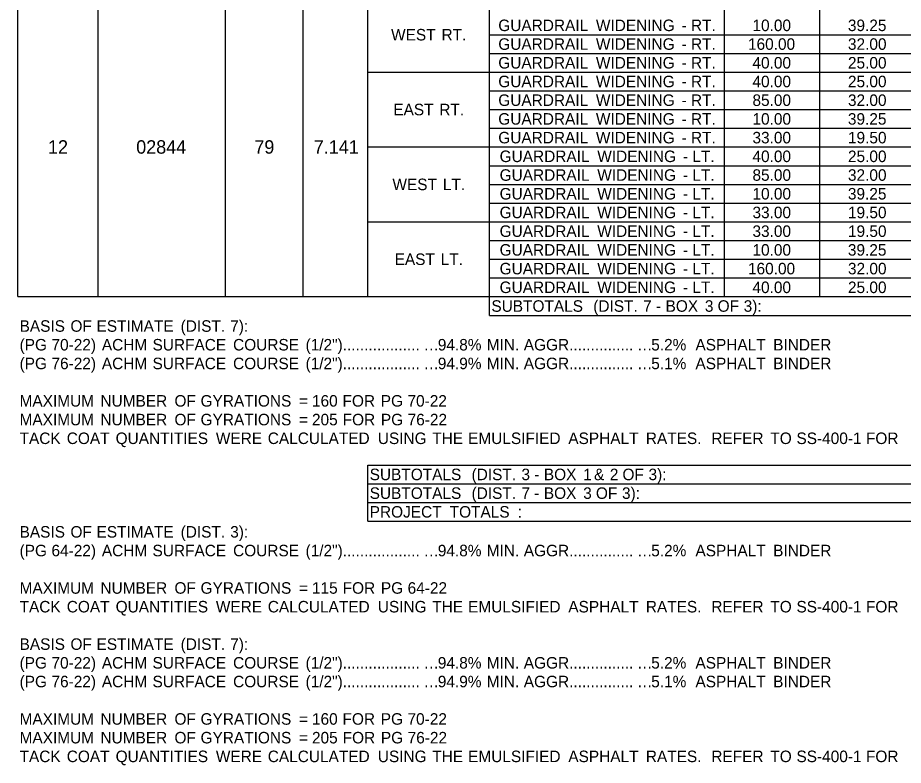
# Model space of a CAD drawing. Extents: x 544478 to 1930787, y -1948294 to 596640.
# Drawn here: x 554061.9 to 554523.1, y -1946916.2 to -1946526.7 of the extents above; entities that cross this region are included whole.
import ezdxf

# ---------------------------------------------------------------- set-up
doc = ezdxf.new("R2010")
doc.units = 0
doc.layers.add('Default', color=7, linetype='Continuous')

msp = doc.modelspace()

# ---------------------------------------------------------------- linework, layer by layer
at = {"layer": 'Default'}
for p, q in [((554061.9, -1946672.02), (554061.9, -1946149.42)), ((554244.23, -1946672.02), (554244.23, -1946149.42)), ((554307.6, -1946681.77), (554307.6, -1946149.42)), ((554429.97, -1946672.02), (554429.97, -1946149.42)), ((554479.69, -1946672.02), (554479.69, -1946149.42)), ((554479.69, -1946672.02), (554479.69, -1946194.27)), ((554103.83, -1946672.02), (554103.83, -1946204.02)), ((554170.13, -1946672.02), (554170.13, -1946204.02)), ((554210.59, -1946672.02), (554210.59, -1946204.02)), ((554429.97, -1946672.02), (554429.97, -1946204.02)), ((554307.6, -1946535.52), (554884.32, -1946535.52)), ((554307.6, -1946545.27), (554884.32, -1946545.27)), ((554244.23, -1946555.02), (554307.6, -1946555.02)), ((554307.6, -1946555.02), (554884.32, -1946555.02)), ((554307.6, -1946564.77), (554884.32, -1946564.77)), ((554307.6, -1946574.52), (554884.32, -1946574.52)), ((554307.6, -1946584.27), (554884.32, -1946584.27)), ((554244.23, -1946594.02), (554307.6, -1946594.02)), ((554307.6, -1946594.02), (554884.32, -1946594.02)), ((554307.6, -1946603.77), (554884.32, -1946603.77)), ((554307.6, -1946613.52), (554884.32, -1946613.52)), ((554307.6, -1946623.27), (554884.32, -1946623.27)), ((554244.23, -1946633.02), (554307.6, -1946633.02)), ((554307.6, -1946633.02), (554581.58, -1946633.02)), ((554307.6, -1946642.77), (554884.32, -1946642.77)), ((554307.6, -1946652.52), (554581.58, -1946652.52)), ((554307.6, -1946662.27), (554581.58, -1946662.27)), ((554061.9, -1946672.02), (554884.32, -1946672.02)), ((554307.6, -1946681.77), (554307.6, -1946672.02)), ((554307.6, -1946681.77), (554884.32, -1946681.77)), ((554244.23, -1946759.77), (554834.59, -1946759.77)), ((554244.23, -1946759.77), (554884.32, -1946759.77)), ((554244.23, -1946789.02), (554244.23, -1946759.77)), ((554244.23, -1946789.02), (554244.23, -1946759.77)), ((554244.23, -1946769.52), (554884.32, -1946769.52)), ((554244.23, -1946779.27), (554884.32, -1946779.27)), ((554244.23, -1946789.02), (554884.32, -1946789.02))]:
    msp.add_line(p, q, dxfattribs=at)

# ---------------------------------------------------------------- texts
for s, height, p in [('GUARDRAIL', 6, (554312.17, -1946533.65)), (' WIDENING', 6, (554360.79, -1946533.65)), (' RT.', 6, (554410.29, -1946533.65)), ('10.00', 6, (554444.54, -1946533.65)), ('39.25', 6, (554494.24, -1946533.65)), ('WEST', 6, (554256.34, -1946538.52)), (' RT.', 6, (554280.39, -1946538.52)), (' -', 6, (554405.44, -1946533.65)), ('GUARDRAIL', 6, (554312.17, -1946543.4)), (' WIDENING', 6, (554360.79, -1946543.4)), (' RT.', 6, (554410.29, -1946543.4)), ('160.00', 6, (554442.21, -1946543.4)), ('32.00', 6, (554494.27, -1946543.4)), (' -', 6, (554405.44, -1946543.4)), ('GUARDRAIL', 6, (554312.17, -1946553.15)), (' WIDENING', 6, (554360.79, -1946553.15)), (' RT.', 6, (554410.29, -1946553.15)), ('40.00', 6, (554444.54, -1946553.15)), ('25.00', 6, (554494.27, -1946553.15)), (' -', 6, (554405.44, -1946553.15)), ('GUARDRAIL', 6, (554312.17, -1946562.9)), (' WIDENING', 6, (554360.79, -1946562.9)), (' RT.', 6, (554410.29, -1946562.9)), ('40.00', 6, (554444.54, -1946562.9)), ('25.00', 6, (554494.27, -1946562.9)), (' -', 6, (554405.44, -1946562.9)), ('GUARDRAIL', 6, (554312.17, -1946572.65)), (' WIDENING', 6, (554360.79, -1946572.65)), (' -', 6, (554405.44, -1946572.65)), (' RT.', 6, (554410.29, -1946572.65)), ('85.00', 6, (554444.54, -1946572.65)), ('32.00', 6, (554494.27, -1946572.65)), ('EAST', 6, (554257.5, -1946577.52)), (' RT.', 6, (554279.23, -1946577.52)), ('GUARDRAIL', 6, (554312.17, -1946582.4)), (' WIDENING', 6, (554360.79, -1946582.4)), (' -', 6, (554405.44, -1946582.4)), (' RT.', 6, (554410.29, -1946582.4)), ('10.00', 6, (554444.54, -1946582.4)), ('39.25', 6, (554494.24, -1946582.4)), ('GUARDRAIL', 6, (554312.17, -1946592.15)), (' WIDENING', 6, (554360.79, -1946592.15)), (' RT.', 6, (554410.29, -1946592.15)), ('33.00', 6, (554444.54, -1946592.15)), ('19.50', 6, (554494.27, -1946592.15)), ('12', 7, (554077.69, -1946597.52)), ('02844', 7, (554123.62, -1946597.52)), ('79', 7, (554185.14, -1946597.52)), ('7.141', 7, (554216.08, -1946597.52)), (' -', 6, (554405.44, -1946592.15)), ('GUARDRAIL', 6, (554312.87, -1946601.9)), (' WIDENING', 6, (554361.49, -1946601.9)), (' LT.', 6, (554410.99, -1946601.9)), ('40.00', 6, (554444.54, -1946601.9)), ('25.00', 6, (554494.27, -1946601.9)), (' -', 6, (554406.14, -1946601.9)), ('GUARDRAIL', 6, (554312.87, -1946611.65)), (' WIDENING', 6, (554361.49, -1946611.65)), (' LT.', 6, (554410.99, -1946611.65)), ('85.00', 6, (554444.54, -1946611.65)), ('32.00', 6, (554494.27, -1946611.65)), ('WEST', 6, (554257.04, -1946616.52)), (' LT.', 6, (554281.09, -1946616.52)), (' -', 6, (554406.14, -1946611.65)), ('GUARDRAIL', 6, (554312.87, -1946621.4)), (' WIDENING', 6, (554361.49, -1946621.4)), (' LT.', 6, (554410.99, -1946621.4)), ('10.00', 6, (554444.54, -1946621.4)), ('39.25', 6, (554494.24, -1946621.4)), (' -', 6, (554406.14, -1946621.4)), ('GUARDRAIL', 6, (554312.87, -1946631.15)), (' WIDENING', 6, (554361.49, -1946631.15)), (' LT.', 6, (554410.99, -1946631.15)), ('33.00', 6, (554444.54, -1946631.15)), ('19.50', 6, (554494.27, -1946631.15)), (' -', 6, (554406.14, -1946631.15)), ('GUARDRAIL', 6, (554312.87, -1946640.9)), (' WIDENING', 6, (554361.49, -1946640.9)), (' LT.', 6, (554410.99, -1946640.9)), ('33.00', 6, (554444.54, -1946640.9)), ('19.50', 6, (554494.27, -1946640.9)), (' -', 6, (554406.14, -1946640.9)), ('GUARDRAIL', 6, (554312.87, -1946650.65)), (' WIDENING', 6, (554361.49, -1946650.65)), (' LT.', 6, (554410.99, -1946650.65)), ('10.00', 6, (554444.54, -1946650.65)), ('39.25', 6, (554494.24, -1946650.65)), (' -', 6, (554406.14, -1946650.65)), ('EAST', 6, (554258.2, -1946655.52)), (' LT.', 6, (554279.93, -1946655.52)), ('GUARDRAIL', 6, (554312.87, -1946660.4)), (' WIDENING', 6, (554361.49, -1946660.4)), (' -', 6, (554406.14, -1946660.4)), (' LT.', 6, (554410.99, -1946660.4)), ('160.00', 6, (554442.21, -1946660.4)), ('32.00', 6, (554494.27, -1946660.4)), ('GUARDRAIL', 6, (554312.87, -1946670.15)), (' WIDENING', 6, (554361.49, -1946670.15)), (' -', 6, (554406.14, -1946670.15)), (' LT.', 6, (554410.99, -1946670.15)), ('40.00', 6, (554444.54, -1946670.15)), ('25.00', 6, (554494.27, -1946670.15)), ('SUBTOTALS', 6, (554308.58, -1946679.9)), (' (DIST.', 6, (554359.4, -1946679.9)), (' 7', 6, (554385.37, -1946679.9)), (' BOX', 6, (554397.05, -1946679.9)), (' 3', 6, (554417.53, -1946679.9)), (' OF', 6, (554424.16, -1946679.9)), (' 3):', 6, (554437.74, -1946679.9)), (' -', 6, (554391.99, -1946679.9)), ('BASIS', 6, (554062.88, -1946690.32)), (' OF', 6, (554087.14, -1946690.32)), (' ESTIMATE', 6, (554100.73, -1946690.32)), (' (DIST.', 6, (554144.53, -1946690.32)), (' 7):', 6, (554170.34, -1946690.32)), ('(PG', 6, (554062.88, -1946700.07)), (' 70-22)', 6, (554077.26, -1946700.07)), (' ACHM', 6, (554103.5, -1946700.07)), (' SURFACE', 6, (554129.88, -1946700.07)), (' COURSE', 6, (554171.83, -1946700.07)), (' (1/2")..................', 6, (554209.58, -1946700.07)), ('94.8%', 6, (554280.68, -1946700.07)), (' MIN.', 6, (554303.92, -1946700.07)), (' AGGR...............', 6, (554323.21, -1946700.07)), ('5.2%', 6, (554391.81, -1946700.07)), ('  ASPHALT', 6, (554410.39, -1946700.07)), (' BINDER', 6, (554453.09, -1946700.07)), ('…', 6, (554273.28, -1946700.07)), ('…', 6, (554384.41, -1946700.07)), ('(PG', 6, (554062.88, -1946709.82)), (' 76-22)', 6, (554077.26, -1946709.82)), (' ACHM', 6, (554103.5, -1946709.82)), (' SURFACE', 6, (554129.88, -1946709.82)), (' COURSE', 6, (554171.83, -1946709.82)), (' (1/2")..................', 6, (554209.58, -1946709.82)), ('94.9%', 6, (554280.68, -1946709.82)), (' MIN.', 6, (554303.92, -1946709.82)), (' AGGR...............', 6, (554323.21, -1946709.82)), ('5.1%', 6, (554391.81, -1946709.82)), ('  ASPHALT', 6, (554410.39, -1946709.82)), (' BINDER', 6, (554453.09, -1946709.82)), ('…', 6, (554273.28, -1946709.82)), ('…', 6, (554384.41, -1946709.82)), ('MAXIMUM', 6, (554062.88, -1946729.32)), (' NUMBER', 6, (554102.76, -1946729.32)), (' OF', 6, (554141.31, -1946729.32)), (' GYRATIONS', 6, (554154.9, -1946729.32)), (' =', 6, (554206.17, -1946729.32)), (' 160', 6, (554212.92, -1946729.32)), (' FOR', 6, (554228.83, -1946729.32)), (' PG', 6, (554248.74, -1946729.32)), (' 70-22', 6, (554262.66, -1946729.32)), ('MAXIMUM', 6, (554062.88, -1946739.07)), (' NUMBER', 6, (554102.76, -1946739.07)), (' OF', 6, (554141.31, -1946739.07)), (' GYRATIONS', 6, (554154.9, -1946739.07)), (' =', 6, (554206.17, -1946739.07)), (' 205', 6, (554212.92, -1946739.07)), (' FOR', 6, (554228.9, -1946739.07)), (' PG', 6, (554248.81, -1946739.07)), (' 76-22', 6, (554262.73, -1946739.07)), ('TACK', 6, (554062.88, -1946748.82)), (' COAT', 6, (554085.22, -1946748.82)), (' QUANTITIES', 6, (554110.67, -1946748.82)), (' WERE', 6, (554162.87, -1946748.82)), (' CALCULATED', 6, (554189.9, -1946748.82)), (' USING', 6, (554247.22, -1946748.82)), (' THE', 6, (554275.58, -1946748.82)), (' EMULSIFIED', 6, (554294.23, -1946748.82)), (' ASPHALT', 6, (554346.41, -1946748.82)), (' RATES.', 6, (554386.78, -1946748.82)), ('  REFER', 6, (554418.66, -1946748.82)), (' TO', 6, (554451.62, -1946748.82)), (' SS-400-1', 6, (554465.22, -1946748.82)), (' FOR', 6, (554501.41, -1946748.82)), ('SUBTOTALS', 6, (554245.2, -1946767.65)), (' (DIST.', 6, (554296.03, -1946767.65)), (' 3', 6, (554322, -1946767.65)), (' BOX', 6, (554333.68, -1946767.65)), (' 1', 6, (554354.17, -1946767.65)), (' &', 6, (554359.8, -1946767.65)), (' 2', 6, (554368.04, -1946767.65)), (' OF', 6, (554374.61, -1946767.65)), (' 3):', 6, (554388.19, -1946767.65)), (' -', 6, (554328.62, -1946767.65)), ('SUBTOTALS', 6, (554245.2, -1946777.4)), (' (DIST.', 6, (554296.03, -1946777.4)), (' 7', 6, (554322, -1946777.4)), (' BOX', 6, (554333.67, -1946777.4)), (' 3', 6, (554354.16, -1946777.4)), (' OF', 6, (554360.78, -1946777.4)), (' 3):', 6, (554374.37, -1946777.4)), (' -', 6, (554328.61, -1946777.4)), ('PROJECT', 6, (554245.2, -1946787.15)), (' TOTALS', 6, (554284.63, -1946787.15)), (' :', 6, (554320.08, -1946787.15)), ('BASIS', 6, (554062.88, -1946797.57)), (' OF', 6, (554087.14, -1946797.57)), (' ESTIMATE', 6, (554100.73, -1946797.57)), (' (DIST.', 6, (554144.53, -1946797.57)), (' 3):', 6, (554170.34, -1946797.57)), ('(PG', 6, (554062.88, -1946807.32)), (' 64-22)', 6, (554077.26, -1946807.32)), (' ACHM', 6, (554103.5, -1946807.32)), (' SURFACE', 6, (554129.88, -1946807.32)), (' COURSE', 6, (554171.83, -1946807.32)), (' (1/2")..................', 6, (554209.58, -1946807.32)), ('94.8%', 6, (554280.68, -1946807.32)), (' MIN.', 6, (554303.92, -1946807.32)), (' AGGR...............', 6, (554323.21, -1946807.32)), ('5.2%', 6, (554391.81, -1946807.32)), ('  ASPHALT', 6, (554410.39, -1946807.32)), (' BINDER', 6, (554453.09, -1946807.32)), ('…', 6, (554273.28, -1946807.32)), ('…', 6, (554384.41, -1946807.32)), ('MAXIMUM', 6, (554062.88, -1946826.82)), (' NUMBER', 6, (554102.76, -1946826.82)), (' OF', 6, (554141.31, -1946826.82)), (' GYRATIONS', 6, (554154.9, -1946826.82)), (' =', 6, (554206.17, -1946826.82)), (' 115', 6, (554212.92, -1946826.82)), (' FOR', 6, (554228.9, -1946826.82)), (' PG', 6, (554248.81, -1946826.82)), (' 64-22', 6, (554262.73, -1946826.82)), ('TACK', 6, (554062.88, -1946836.57)), (' COAT', 6, (554085.22, -1946836.57)), (' QUANTITIES', 6, (554110.67, -1946836.57)), (' WERE', 6, (554162.87, -1946836.57)), (' CALCULATED', 6, (554189.9, -1946836.57)), (' USING', 6, (554247.22, -1946836.57)), (' THE', 6, (554275.58, -1946836.57)), (' EMULSIFIED', 6, (554294.23, -1946836.57)), (' ASPHALT', 6, (554346.41, -1946836.57)), (' RATES.', 6, (554386.78, -1946836.57)), ('  REFER', 6, (554418.66, -1946836.57)), (' TO', 6, (554451.62, -1946836.57)), (' SS-400-1', 6, (554465.22, -1946836.57)), (' FOR', 6, (554501.41, -1946836.57)), ('BASIS', 6, (554062.88, -1946856.07)), (' OF', 6, (554087.14, -1946856.07)), (' ESTIMATE', 6, (554100.73, -1946856.07)), (' (DIST.', 6, (554144.53, -1946856.07)), (' 7):', 6, (554170.34, -1946856.07)), ('(PG', 6, (554062.88, -1946865.82)), (' 70-22)', 6, (554077.26, -1946865.82)), (' ACHM', 6, (554103.5, -1946865.82)), (' SURFACE', 6, (554129.88, -1946865.82)), (' COURSE', 6, (554171.83, -1946865.82)), (' (1/2")..................', 6, (554209.58, -1946865.82)), ('94.8%', 6, (554280.68, -1946865.82)), (' MIN.', 6, (554303.92, -1946865.82)), (' AGGR...............', 6, (554323.21, -1946865.82)), ('5.2%', 6, (554391.81, -1946865.82)), ('  ASPHALT', 6, (554410.39, -1946865.82)), (' BINDER', 6, (554453.09, -1946865.82)), ('…', 6, (554273.28, -1946865.82)), ('…', 6, (554384.41, -1946865.82)), ('(PG', 6, (554062.88, -1946875.57)), (' 76-22)', 6, (554077.26, -1946875.57)), (' ACHM', 6, (554103.5, -1946875.57)), (' SURFACE', 6, (554129.88, -1946875.57)), (' COURSE', 6, (554171.83, -1946875.57)), (' (1/2")..................', 6, (554209.58, -1946875.57)), ('94.9%', 6, (554280.68, -1946875.57)), (' MIN.', 6, (554303.92, -1946875.57)), (' AGGR...............', 6, (554323.21, -1946875.57)), ('5.1%', 6, (554391.81, -1946875.57)), ('  ASPHALT', 6, (554410.39, -1946875.57)), (' BINDER', 6, (554453.09, -1946875.57)), ('…', 6, (554273.28, -1946875.57)), ('…', 6, (554384.41, -1946875.57)), ('MAXIMUM', 6, (554062.88, -1946895.07)), (' NUMBER', 6, (554102.76, -1946895.07)), (' OF', 6, (554141.31, -1946895.07)), (' GYRATIONS', 6, (554154.9, -1946895.07)), (' 160', 6, (554212.92, -1946895.07)), (' FOR', 6, (554228.83, -1946895.07)), (' PG', 6, (554248.74, -1946895.07)), (' 70-22', 6, (554262.66, -1946895.07)), (' =', 6, (554206.17, -1946895.07)), ('MAXIMUM', 6, (554062.88, -1946904.82)), (' NUMBER', 6, (554102.76, -1946904.82)), (' OF', 6, (554141.31, -1946904.82)), (' GYRATIONS', 6, (554154.9, -1946904.82)), (' =', 6, (554206.17, -1946904.82)), (' 205', 6, (554212.92, -1946904.82)), (' FOR', 6, (554228.9, -1946904.82)), (' PG', 6, (554248.81, -1946904.82)), (' 76-22', 6, (554262.73, -1946904.82)), ('TACK', 6, (554062.88, -1946914.57)), (' COAT', 6, (554085.22, -1946914.57)), (' QUANTITIES', 6, (554110.67, -1946914.57)), (' WERE', 6, (554162.87, -1946914.57)), (' CALCULATED', 6, (554189.9, -1946914.57)), (' USING', 6, (554247.22, -1946914.57)), (' THE', 6, (554275.58, -1946914.57)), (' EMULSIFIED', 6, (554294.23, -1946914.57)), (' ASPHALT', 6, (554346.41, -1946914.57)), (' RATES.', 6, (554386.78, -1946914.57)), ('  REFER', 6, (554418.66, -1946914.57)), (' TO', 6, (554451.62, -1946914.57)), (' SS-400-1', 6, (554465.22, -1946914.57)), (' FOR', 6, (554501.41, -1946914.57))]:
    msp.add_text(s, height=height, dxfattribs=at).set_placement(p)

doc.saveas('drawing.dxf')
